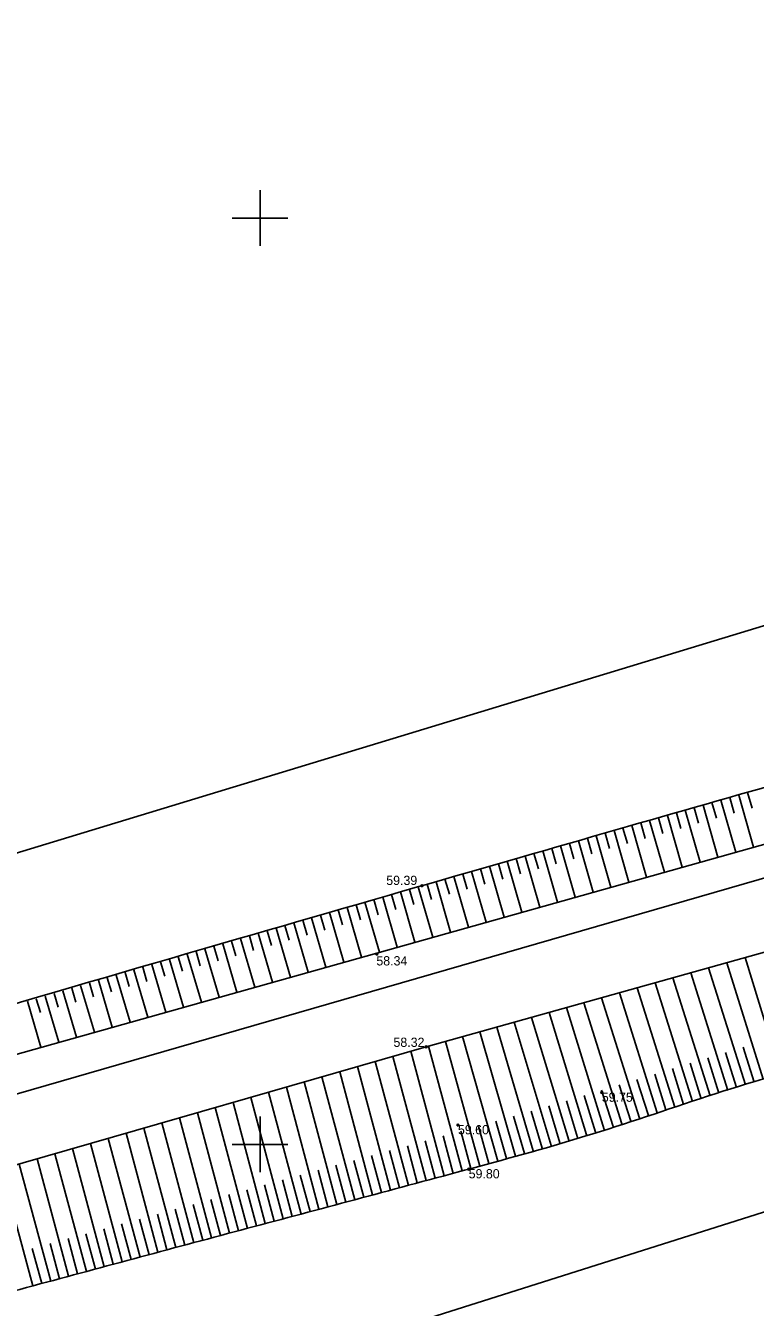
# Model space of a CAD drawing. Extents: x 616607 to 617499, y 408385 to 409695.
# Drawn here: x 616837.3 to 616876.8, y 408541.2 to 408610.4 of the extents above; entities that cross this region are included whole.
import ezdxf

# ---------------------------------------------------------------- set-up
doc = ezdxf.new("R2010")
doc.units = 0
for name, color, linetype in [('GEOD_ELEM_####_####_#', 7, 'Continuous'), ('HIDG_GRAV_####_####_#', 7, 'Continuous'), ('RAMI_UZMR_####_####_#', 7, 'Continuous'), ('RELJ_AATZ_####_TKST_#', 7, 'Continuous'), ('RELJ_ELEM_####_####_#', 7, 'Continuous'), ('RELJ_NOGA_####_####_#', 7, 'Continuous'), ('ROBZ_IERR_####_####_#', 7, 'Continuous'), ('ROBZ_UZMR_####_####_#', 7, 'Continuous')]:
    doc.layers.add(name, color=color, linetype=linetype)

# ---------------------------------------------------------------- blocks, each defined once
blk = doc.blocks.new('PKT')
at = {"layer": 'RELJ_ELEM_####_####_#'}
blk.add_circle((0, 0), 0.05, dxfattribs=at)
blk = doc.blocks.new('KRUSTS')
at = {"layer": 'GEOD_ELEM_####_####_#'}
for p, q in [((0, 1.5), (0, 0)), ((-1.5, 0), (0, 0)), ((0, 0), (0, -1.5)), ((0, 0), (1.5, 0))]:
    blk.add_line(p, q, dxfattribs=at)

msp = doc.modelspace()

# ---------------------------------------------------------------- linework, layer by layer
at = {"layer": 'HIDG_GRAV_####_####_#'}
for points in [[(616726.56, 408522.413), (616768.796, 408535.775), (616917.84, 408577.602)], [(616935.727, 408576.737), (616858.974, 408555.268), (616829.937, 408546.914), (616828.609, 408549.04), (616825.59, 408548.927), (616826.098, 408546.263), (616824.758, 408545.383), (616765.45, 408526.57), (616717.618, 408497.675)]]:
    msp.add_lwpolyline(points, dxfattribs=at)
at = {"layer": 'RAMI_UZMR_####_####_#'}
for points in [[(617191.828, 409115.62), (617145.545, 408952.8), (617072.809, 408766.141), (616965.332, 408652.076), (616939.432, 408594.661), (616924.839, 408592.467), (616706.433, 408526.081), (616666.426, 408467.691)], [(616666.426, 408467.691), (616675.529, 408457.882), (616687.228, 408463.356), (616723.888, 408465.775), (616753.554, 408507.232), (616948.282, 408568.831), (616981.528, 408608.531), (617014.563, 408672.892), (617101.571, 408748.246), (617213.472, 409074.039)]]:
    msp.add_lwpolyline(points, dxfattribs=at)
at = {"layer": 'RELJ_NOGA_####_####_#'}
for p, q in [((616876.333, 408568.996), (616876.573, 408568.151)), ((616876.333, 408568.996), (616876.333, 408568.996)), ((616873.928, 408568.311), (616874.729, 408565.504)), ((616873.928, 408568.311), (616873.928, 408568.31)), ((616874.409, 408568.448), (616874.649, 408567.605)), ((616874.409, 408568.448), (616874.409, 408568.448)), ((616874.89, 408568.585), (616875.691, 408565.773)), ((616874.89, 408568.585), (616874.89, 408568.584)), ((616875.371, 408568.722), (616875.611, 408567.878)), ((616875.371, 408568.722), (616875.371, 408568.722)), ((616875.852, 408568.859), (616876.653, 408566.044)), ((616875.852, 408568.859), (616875.852, 408568.858)), ((616871.524, 408567.626), (616871.763, 408566.786)), ((616871.524, 408567.626), (616871.524, 408567.625)), ((616872.005, 408567.763), (616872.803, 408564.963)), ((616872.005, 408567.763), (616872.005, 408567.762)), ((616872.486, 408567.9), (616872.725, 408567.059)), ((616872.486, 408567.9), (616872.486, 408567.9)), ((616872.967, 408568.037), (616873.766, 408565.233)), ((616872.967, 408568.037), (616872.967, 408568.036)), ((616873.447, 408568.174), (616873.687, 408567.332)), ((616873.447, 408568.174), (616873.447, 408568.174)), ((616869.12, 408566.939), (616869.916, 408564.153)), ((616869.12, 408566.939), (616869.12, 408566.938)), ((616869.601, 408567.076), (616869.84, 408566.24)), ((616869.601, 408567.076), (616869.601, 408567.076)), ((616870.082, 408567.214), (616870.879, 408564.423)), ((616870.082, 408567.214), (616870.082, 408567.213)), ((616870.562, 408567.351), (616870.802, 408566.513)), ((616870.562, 408567.351), (616870.563, 408567.351)), ((616871.043, 408567.488), (616871.842, 408564.693)), ((616871.043, 408567.488), (616871.044, 408567.487)), ((616866.717, 408566.252), (616866.955, 408565.42)), ((616866.717, 408566.252), (616866.717, 408566.251)), ((616867.197, 408566.389), (616867.991, 408563.613)), ((616867.197, 408566.389), (616867.197, 408566.388)), ((616867.678, 408566.527), (616867.916, 408565.693)), ((616867.678, 408566.527), (616867.678, 408566.527)), ((616868.159, 408566.664), (616868.954, 408563.883)), ((616868.159, 408566.664), (616868.159, 408566.663)), ((616868.639, 408566.802), (616868.878, 408565.967)), ((616868.639, 408566.802), (616868.639, 408566.802)), ((616864.313, 408565.563), (616865.104, 408562.803)), ((616864.313, 408565.563), (616864.313, 408565.562)), ((616864.794, 408565.701), (616865.031, 408564.872)), ((616864.794, 408565.701), (616864.794, 408565.701)), ((616865.274, 408565.839), (616866.067, 408563.073)), ((616865.274, 408565.839), (616865.275, 408565.838)), ((616865.755, 408565.976), (616865.993, 408565.146)), ((616865.755, 408565.976), (616865.755, 408565.976)), ((616866.236, 408566.114), (616867.029, 408563.343)), ((616866.236, 408566.114), (616866.236, 408566.113)), ((616861.91, 408564.874), (616862.147, 408564.05)), ((616861.91, 408564.874), (616861.91, 408564.873)), ((616862.391, 408565.012), (616863.18, 408562.262)), ((616862.391, 408565.012), (616862.391, 408565.011)), ((616862.871, 408565.15), (616863.108, 408564.324)), ((616862.871, 408565.15), (616862.871, 408565.149)), ((616863.352, 408565.287), (616864.143, 408562.533)), ((616863.352, 408565.287), (616863.352, 408565.287)), ((616863.833, 408565.425), (616864.07, 408564.598)), ((616863.833, 408565.425), (616863.833, 408565.425)), ((616859.508, 408564.183), (616860.293, 408561.452)), ((616859.508, 408564.183), (616859.508, 408564.182)), ((616859.988, 408564.321), (616860.224, 408563.501)), ((616859.988, 408564.321), (616859.988, 408564.321)), ((616860.469, 408564.459), (616861.256, 408561.723)), ((616860.469, 408564.459), (616860.469, 408564.458)), ((616860.949, 408564.597), (616861.185, 408563.775)), ((616860.949, 408564.597), (616860.949, 408564.597)), ((616861.43, 408564.736), (616862.218, 408561.993)), ((616861.43, 408564.736), (616861.43, 408564.735)), ((616857.105, 408563.49), (616857.341, 408562.677)), ((616857.105, 408563.49), (616857.105, 408563.49)), ((616857.586, 408563.629), (616858.369, 408560.912)), ((616857.586, 408563.629), (616857.586, 408563.628)), ((616858.066, 408563.768), (616858.301, 408562.952)), ((616858.066, 408563.768), (616858.066, 408563.767)), ((616858.547, 408563.906), (616859.332, 408561.183)), ((616858.547, 408563.906), (616858.547, 408563.905)), ((616859.027, 408564.045), (616859.262, 408563.226)), ((616859.027, 408564.045), (616859.027, 408564.044)), ((616854.704, 408562.795), (616855.484, 408560.103)), ((616854.704, 408562.795), (616854.704, 408562.794)), ((616855.184, 408562.934), (616855.419, 408562.126)), ((616855.184, 408562.934), (616855.184, 408562.934)), ((616855.664, 408563.074), (616856.446, 408560.373)), ((616855.664, 408563.074), (616855.665, 408563.073)), ((616856.145, 408563.213), (616856.379, 408562.401)), ((616856.145, 408563.213), (616856.145, 408563.212)), ((616856.625, 408563.351), (616857.408, 408560.643)), ((616856.625, 408563.351), (616856.625, 408563.351)), ((616852.303, 408562.097), (616852.536, 408561.297)), ((616852.303, 408562.097), (616852.303, 408562.097)), ((616852.783, 408562.237), (616853.562, 408559.563)), ((616852.783, 408562.237), (616852.784, 408562.236)), ((616853.263, 408562.377), (616853.497, 408561.573)), ((616853.263, 408562.377), (616853.264, 408562.377)), ((616853.744, 408562.516), (616854.523, 408559.833)), ((616853.744, 408562.516), (616853.744, 408562.515)), ((616854.224, 408562.656), (616854.458, 408561.85)), ((616854.224, 408562.656), (616854.224, 408562.656)), ((616849.903, 408561.397), (616850.676, 408558.754)), ((616849.903, 408561.397), (616849.904, 408561.396)), ((616850.383, 408561.538), (616850.615, 408560.743)), ((616850.383, 408561.538), (616850.383, 408561.537)), ((616850.863, 408561.678), (616851.638, 408559.023)), ((616850.863, 408561.678), (616850.864, 408561.677)), ((616851.343, 408561.818), (616851.576, 408561.02)), ((616851.343, 408561.818), (616851.343, 408561.817)), ((616851.823, 408561.958), (616852.599, 408559.293)), ((616851.823, 408561.958), (616851.824, 408561.957)), ((616847.504, 408560.695), (616847.734, 408559.91)), ((616847.504, 408560.695), (616847.504, 408560.695)), ((616847.984, 408560.836), (616848.752, 408558.213)), ((616847.984, 408560.836), (616847.984, 408560.835)), ((616848.464, 408560.976), (616848.694, 408560.188)), ((616848.464, 408560.976), (616848.464, 408560.976)), ((616848.944, 408561.117), (616849.714, 408558.484)), ((616848.944, 408561.117), (616848.944, 408561.116)), ((616849.423, 408561.257), (616849.655, 408560.465)), ((616849.423, 408561.257), (616849.423, 408561.257)), ((616845.105, 408559.991), (616845.866, 408557.404)), ((616845.105, 408559.991), (616845.106, 408559.99)), ((616845.585, 408560.132), (616845.814, 408559.354)), ((616845.585, 408560.132), (616845.585, 408560.131)), ((616846.065, 408560.273), (616846.829, 408557.674)), ((616846.065, 408560.273), (616846.065, 408560.272)), ((616846.544, 408560.413), (616846.774, 408559.632)), ((616846.544, 408560.413), (616846.545, 408560.413)), ((616847.024, 408560.554), (616847.79, 408557.944)), ((616847.024, 408560.554), (616847.025, 408560.553)), ((616878.128, 408553.811), (616876.199, 408560.086)), ((616842.707, 408559.285), (616842.933, 408558.518)), ((616842.707, 408559.285), (616842.707, 408559.284)), ((616843.187, 408559.426), (616843.941, 408556.864)), ((616843.187, 408559.426), (616843.187, 408559.425)), ((616843.666, 408559.567), (616843.893, 408558.797)), ((616843.666, 408559.567), (616843.666, 408559.567)), ((616844.146, 408559.708), (616844.904, 408557.134)), ((616844.146, 408559.708), (616844.146, 408559.707)), ((616844.626, 408559.85), (616844.853, 408559.075)), ((616844.626, 408559.85), (616844.626, 408559.849)), ((616875.265, 408552.917), (616873.264, 408559.265)), ((616876.218, 408553.217), (616874.228, 408559.535)), ((616877.173, 408553.516), (616875.216, 408559.811)), ((616840.309, 408558.577), (616841.054, 408556.053)), ((616840.309, 408558.577), (616840.31, 408558.576)), ((616840.789, 408558.719), (616841.013, 408557.96)), ((616840.789, 408558.719), (616840.789, 408558.718)), ((616841.268, 408558.86), (616842.017, 408556.324)), ((616841.268, 408558.86), (616841.269, 408558.859)), ((616841.748, 408559.002), (616841.973, 408558.239)), ((616841.748, 408559.002), (616841.748, 408559.001)), ((616842.227, 408559.143), (616842.98, 408556.594)), ((616842.227, 408559.143), (616842.228, 408559.142)), ((616873.357, 408552.316), (616871.337, 408558.726)), ((616874.311, 408552.616), (616872.3, 408558.996)), ((616837.912, 408557.868), (616838.133, 408557.121)), ((616837.912, 408557.868), (616837.912, 408557.868)), ((616838.391, 408558.01), (616839.13, 408555.513)), ((616838.391, 408558.01), (616838.392, 408558.009)), ((616838.871, 408558.152), (616839.093, 408557.401)), ((616838.871, 408558.152), (616838.871, 408558.151)), ((616839.35, 408558.294), (616840.093, 408555.783)), ((616839.35, 408558.294), (616839.351, 408558.293)), ((616839.83, 408558.435), (616840.053, 408557.68)), ((616839.83, 408558.435), (616839.83, 408558.435)), ((616870.496, 408551.414), (616868.446, 408557.918)), ((616871.45, 408551.715), (616869.41, 408558.187)), ((616872.403, 408552.015), (616870.373, 408558.457)), ((616837.432, 408557.726), (616838.167, 408555.243)), ((616837.432, 408557.726), (616837.433, 408557.725)), ((616868.588, 408550.815), (616866.544, 408557.386)), ((616869.542, 408551.113), (616867.483, 408557.648)), ((616865.718, 408549.939), (616863.727, 408556.598)), ((616866.676, 408550.228), (616864.663, 408556.86)), ((616867.632, 408550.52), (616865.608, 408557.124)), ((616862.838, 408549.102), (616860.939, 408555.818)), ((616863.799, 408549.376), (616861.874, 408556.08)), ((616864.76, 408549.655), (616862.794, 408556.337)), ((616860.909, 408548.572), (616859.094, 408555.302)), ((616861.874, 408548.834), (616860.025, 408555.562)), ((616876.695, 408553.368), (616876.1, 408555.258)), ((616858.012, 408547.793), (616856.222, 408554.477)), ((616858.978, 408548.052), (616857.179, 408554.752)), ((616859.944, 408548.311), (616858.137, 408555.028)), ((616874.788, 408552.766), (616874.186, 408554.676)), ((616875.742, 408553.067), (616875.143, 408554.967)), ((616856.08, 408547.275), (616854.304, 408553.925)), ((616857.046, 408547.534), (616855.261, 408554.2)), ((616871.926, 408551.865), (616871.316, 408553.802)), ((616872.88, 408552.165), (616872.273, 408554.093)), ((616873.834, 408552.466), (616873.229, 408554.384)), ((616853.182, 408546.502), (616851.424, 408553.096)), ((616854.148, 408546.76), (616852.385, 408553.373)), ((616855.114, 408547.017), (616853.342, 408553.648)), ((616870.019, 408551.264), (616869.403, 408553.22)), ((616870.973, 408551.564), (616870.359, 408553.511)), ((616875.742, 408553.067), (616875.741, 408553.067)), ((616876.218, 408553.217), (616876.218, 408553.218)), ((616876.695, 408553.368), (616876.695, 408553.368)), ((616851.249, 408545.987), (616849.501, 408552.543)), ((616852.215, 408546.244), (616850.462, 408552.819)), ((616867.154, 408550.373), (616866.548, 408552.359)), ((616868.11, 408550.667), (616867.498, 408552.643)), ((616869.065, 408550.963), (616868.446, 408552.928)), ((616873.834, 408552.466), (616873.834, 408552.466)), ((616874.311, 408552.616), (616874.311, 408552.617)), ((616874.788, 408552.766), (616874.788, 408552.767)), ((616875.265, 408552.917), (616875.264, 408552.918)), ((616848.35, 408545.214), (616846.617, 408551.713)), ((616849.317, 408545.471), (616847.578, 408551.99)), ((616850.283, 408545.729), (616848.54, 408552.266)), ((616865.239, 408549.797), (616864.645, 408551.798)), ((616866.197, 408550.083), (616865.598, 408552.077)), ((616871.45, 408551.715), (616871.449, 408551.715)), ((616871.926, 408551.865), (616871.926, 408551.865)), ((616872.403, 408552.015), (616872.403, 408552.016)), ((616872.88, 408552.165), (616872.88, 408552.166)), ((616873.357, 408552.316), (616873.357, 408552.317)), ((616846.418, 408544.698), (616844.691, 408551.159)), ((616847.384, 408544.956), (616845.653, 408551.436)), ((616862.356, 408548.967), (616861.796, 408550.985)), ((616863.319, 408549.238), (616862.744, 408551.251)), ((616864.28, 408549.515), (616863.694, 408551.522)), ((616869.065, 408550.963), (616869.065, 408550.963)), ((616869.542, 408551.113), (616869.542, 408551.114)), ((616870.019, 408551.264), (616870.019, 408551.264)), ((616870.496, 408551.414), (616870.496, 408551.415)), ((616870.973, 408551.564), (616870.973, 408551.565)), ((616843.52, 408543.921), (616841.8, 408550.327)), ((616844.486, 408544.18), (616842.763, 408550.604)), ((616845.452, 408544.439), (616843.727, 408550.882)), ((616860.426, 408548.441), (616859.882, 408550.458)), ((616861.392, 408548.702), (616860.843, 408550.721)), ((616867.154, 408550.373), (616867.154, 408550.373)), ((616867.632, 408550.52), (616867.632, 408550.52)), ((616868.11, 408550.667), (616868.11, 408550.667)), ((616868.588, 408550.815), (616868.587, 408550.816)), ((616841.589, 408543.402), (616839.878, 408549.774)), ((616842.555, 408543.662), (616840.839, 408550.051)), ((616857.529, 408547.663), (616856.993, 408549.666)), ((616858.495, 408547.922), (616857.956, 408549.93)), ((616859.461, 408548.182), (616858.919, 408550.194)), ((616864.76, 408549.655), (616864.759, 408549.656)), ((616865.239, 408549.797), (616865.239, 408549.797)), ((616865.718, 408549.939), (616865.718, 408549.94)), ((616866.197, 408550.083), (616866.197, 408550.083)), ((616866.676, 408550.228), (616866.676, 408550.229)), ((616838.691, 408542.624), (616836.994, 408548.944)), ((616839.657, 408542.884), (616837.956, 408549.221)), ((616840.623, 408543.143), (616838.917, 408549.498)), ((616854.631, 408546.888), (616854.101, 408548.875)), ((616855.597, 408547.146), (616855.065, 408549.138)), ((616856.563, 408547.405), (616856.028, 408549.402)), ((616862.356, 408548.967), (616862.356, 408548.967)), ((616862.838, 408549.102), (616862.837, 408549.103)), ((616863.319, 408549.238), (616863.319, 408549.238)), ((616863.799, 408549.376), (616863.799, 408549.377)), ((616864.28, 408549.515), (616864.28, 408549.515)), ((616837.726, 408542.365), (616836.033, 408548.668)), ((616852.698, 408546.373), (616852.172, 408548.349)), ((616853.665, 408546.631), (616853.137, 408548.612)), ((616859.461, 408548.182), (616859.461, 408548.182)), ((616859.944, 408548.311), (616859.943, 408548.312)), ((616860.426, 408548.441), (616860.426, 408548.442)), ((616860.909, 408548.572), (616860.909, 408548.573)), ((616861.392, 408548.702), (616861.392, 408548.702)), ((616861.874, 408548.834), (616861.874, 408548.835)), ((616849.8, 408545.6), (616849.278, 408547.559)), ((616850.766, 408545.858), (616850.242, 408547.822)), ((616851.732, 408546.116), (616851.207, 408548.085)), ((616857.046, 408547.534), (616857.046, 408547.535)), ((616857.529, 408547.663), (616857.529, 408547.664)), ((616858.012, 408547.793), (616858.012, 408547.794)), ((616858.495, 408547.922), (616858.495, 408547.922)), ((616858.978, 408548.052), (616858.978, 408548.053)), ((616847.867, 408545.085), (616847.347, 408547.032)), ((616848.833, 408545.343), (616848.313, 408547.295)), ((616854.631, 408546.888), (616854.631, 408546.889)), ((616855.114, 408547.017), (616855.114, 408547.018)), ((616855.597, 408547.146), (616855.597, 408547.147)), ((616856.08, 408547.275), (616856.08, 408547.276)), ((616856.563, 408547.405), (616856.563, 408547.405)), ((616844.969, 408544.31), (616844.452, 408546.24)), ((616845.935, 408544.568), (616845.417, 408546.504)), ((616846.901, 408544.827), (616846.382, 408546.768)), ((616851.732, 408546.116), (616851.732, 408546.116)), ((616852.215, 408546.244), (616852.215, 408546.245)), ((616852.698, 408546.373), (616852.698, 408546.373)), ((616853.182, 408546.502), (616853.181, 408546.503)), ((616853.665, 408546.631), (616853.665, 408546.631)), ((616854.148, 408546.76), (616854.148, 408546.761)), ((616842.072, 408543.532), (616841.558, 408545.446)), ((616843.037, 408543.791), (616842.522, 408545.711)), ((616844.003, 408544.051), (616843.487, 408545.975)), ((616849.317, 408545.471), (616849.316, 408545.472)), ((616849.8, 408545.6), (616849.8, 408545.601)), ((616850.283, 408545.729), (616850.283, 408545.73)), ((616850.766, 408545.858), (616850.766, 408545.858)), ((616851.249, 408545.987), (616851.249, 408545.988)), ((616840.14, 408543.013), (616839.629, 408544.917)), ((616841.106, 408543.273), (616840.593, 408545.182)), ((616846.901, 408544.827), (616846.901, 408544.827)), ((616847.384, 408544.956), (616847.384, 408544.957)), ((616847.867, 408545.085), (616847.867, 408545.085)), ((616848.35, 408545.214), (616848.35, 408545.215)), ((616848.833, 408545.343), (616848.833, 408545.343)), ((616838.209, 408542.495), (616837.7, 408544.388)), ((616839.174, 408542.754), (616838.664, 408544.653)), ((616844.003, 408544.051), (616844.003, 408544.051)), ((616844.486, 408544.18), (616844.486, 408544.181)), ((616844.969, 408544.31), (616844.969, 408544.31)), ((616845.452, 408544.439), (616845.452, 408544.44)), ((616845.935, 408544.568), (616845.935, 408544.569)), ((616846.418, 408544.698), (616846.418, 408544.699)), ((616841.589, 408543.402), (616841.588, 408543.403)), ((616842.072, 408543.532), (616842.072, 408543.532)), ((616842.555, 408543.662), (616842.554, 408543.663)), ((616843.037, 408543.791), (616843.037, 408543.792)), ((616843.52, 408543.921), (616843.52, 408543.922)), ((616839.174, 408542.754), (616839.174, 408542.754)), ((616839.657, 408542.884), (616839.657, 408542.885)), ((616840.14, 408543.013), (616840.14, 408543.014)), ((616840.623, 408543.143), (616840.623, 408543.144)), ((616841.106, 408543.273), (616841.106, 408543.273)), ((616837.726, 408542.365), (616837.725, 408542.366)), ((616838.209, 408542.495), (616838.208, 408542.495)), ((616838.691, 408542.624), (616838.691, 408542.625))]:
    msp.add_line(p, q, dxfattribs=at)
msp.add_open_spline([(616975.731, 408606.41), (616971.71, 408604.144), (616967.689, 408601.878), (616963.668, 408599.612), (616962.341, 408598.864), (616961.192, 408597.791), (616960.311, 408596.511), (616959.39, 408595.173), (616958.675, 408593.776), (616958.002, 408592.329), (616957.302, 408590.825), (616956.736, 408589.272), (616956.015, 408587.778), (616955.313, 408586.324), (616954.582, 408584.882), (616953.626, 408583.572), (616952.496, 408582.025), (616951.261, 408580.593), (616950.022, 408579.143), (616948.785, 408577.695), (616947.537, 408576.278), (616946.22, 408574.895), (616945.626, 408574.271), (616944.957, 408573.742), (616944.225, 408573.278), (616943.451, 408572.788), (616942.648, 408572.387), (616941.804, 408572.051), (616941, 408571.73), (616940.2, 408571.414), (616939.368, 408571.187), (616938.69, 408571.002), (616938.005, 408570.852), (616937.329, 408570.663), (616918.615, 408565.441), (616899.903, 408560.204), (616881.253, 408554.75), (616874.57, 408552.796), (616867.991, 408550.484), (616861.269, 408548.669), (616855.483, 408547.106), (616849.688, 408545.577), (616843.9, 408544.023), (616838.111, 408542.469), (616832.323, 408540.916), (616826.537, 408539.352), (616816.497, 408536.637), (616806.51, 408533.737), (616796.541, 408530.774), (616791.553, 408529.292), (616786.584, 408527.751), (616781.609, 408526.226), (616776.622, 408524.697), (616771.656, 408523.11), (616766.688, 408521.515), (616762.607, 408520.204), (616758.677, 408518.521), (616754.775, 408516.687), (616750.921, 408514.875), (616747.341, 408512.653), (616743.915, 408510.109), (616740.341, 408507.454), (616736.942, 408504.677), (616733.801, 408501.555), (616732.131, 408499.895), (616730.49, 408498.223), (616728.926, 408496.468), (616728.114, 408495.556), (616727.318, 408494.632), (616726.518, 408493.709), (616725.695, 408492.76), (616724.91, 408491.864), (616724.122, 408490.803), (616723.665, 408490.187), (616723.18, 408489.459), (616723.332, 408488.764), (616723.537, 408487.829), (616723.949, 408486.896), (616724.213, 408485.954), (616724.975, 408483.236), (616725.742, 408480.486), (616726.381, 408477.738), (616726.631, 408476.667), (616726.554, 408475.507), (616726.221, 408474.429), (616726.043, 408473.855), (616725.77, 408473.346), (616725.415, 408472.86), (616725.226, 408472.602), (616725.032, 408472.37), (616724.813, 408472.14), (616724.582, 408471.898), (616724.347, 408471.683), (616724.071, 408471.48), (616723.783, 408471.268), (616723.475, 408471.091), (616723.13, 408471.039), (616722.812, 408470.991), (616722.494, 408470.986), (616722.176, 408470.982), (616721.543, 408470.975), (616720.901, 408471.154), (616720.278, 408471.02), (616716.569, 408470.219), (616712.93, 408469.339), (616709.261, 408468.478), (616707.424, 408468.047), (616705.589, 408467.613), (616703.751, 408467.182), (616701.927, 408466.754), (616700.076, 408466.424), (616698.236, 408466.115), (616695.42, 408465.64), (616692.315, 408465.565), (616689.691, 408467.073), (616684.319, 408470.158), (616679.892, 408473.486), (616675.008, 408476.777), (616674.831, 408476.896), (616674.652, 408477.012), (616674.483, 408477.14), (616674.175, 408477.376), (616674.46, 408477.978), (616674.696, 408478.288), (616675.427, 408479.251), (616676.165, 408480.2), (616676.939, 408481.135), (616677.893, 408482.289), (616678.812, 408483.429), (616679.848, 408484.532), (616681.078, 408485.839), (616682.698, 408486.726), (616684.412, 408487.237), (616686.183, 408487.764), (616687.958, 408488.143), (616689.768, 408488.401), (616691.642, 408488.668), (616693.528, 408488.826), (616695.398, 408489.116), (616696.323, 408489.26), (616697.239, 408489.444), (616698.155, 408489.647), (616699.054, 408489.848), (616699.912, 408490.166), (616700.785, 408490.476), (616703.122, 408491.305), (616705.613, 408491.942), (616707.248, 408494.043), (616707.429, 408494.275), (616707.474, 408494.537), (616707.552, 408494.798), (616707.628, 408495.051), (616707.711, 408495.3), (616707.761, 408495.559), (616707.86, 408496.068), (616707.943, 408496.577), (616707.977, 408497.092), (616708.044, 408498.12), (616708.108, 408499.147), (616708.168, 408500.175), (616708.254, 408501.63), (616708.34, 408503.085), (616708.414, 408504.54), (616708.488, 408505.998), (616708.403, 408507.461), (616708.436, 408508.92), (616708.468, 408510.38), (616708.539, 408511.837), (616708.686, 408513.293), (616708.76, 408514.026), (616708.887, 408514.749), (616709.039, 408515.47), (616709.116, 408515.834), (616709.208, 408516.193), (616709.297, 408516.554), (616709.387, 408516.92), (616709.487, 408517.278), (616709.619, 408517.635), (616710.681, 408520.51), (616712.959, 408522.898), (616715.736, 408524.335), (616718.688, 408525.863), (616721.668, 408526.887), (616724.792, 408527.643), (616730.078, 408528.922), (616735.359, 408530.207), (616740.655, 408531.436), (616749.901, 408533.581), (616759.244, 408535.317), (616768.413, 408537.779), (616798.7, 408545.91), (616828.618, 408555.288), (616858.746, 408563.964), (616877.646, 408569.406), (616896.581, 408574.731), (616915.501, 408580.089), (616916.131, 408580.267), (616916.803, 408580.127), (616917.44, 408580.402), (616917.832, 408580.571), (616918.181, 408580.992), (616918.136, 408581.394), (616918.071, 408581.969), (616918.005, 408582.544), (616917.94, 408583.119), (616917.87, 408583.733), (616917.799, 408584.347), (616917.73, 408584.96), (616917.674, 408585.454), (616917.97, 408585.948), (616918.384, 408586.3), (616918.906, 408586.742), (616919.445, 408586.959), (616920.02, 408587.218), (616920.568, 408587.465), (616921.093, 408587.698), (616921.676, 408587.899), (616922.792, 408588.284), (616923.918, 408588.529), (616925.044, 408588.565), (616925.938, 408588.594), (616926.854, 408588.454), (616927.734, 408588.123), (616928.677, 408587.768), (616929.526, 408587.359), (616930.432, 408586.999), (616931.324, 408586.645), (616932.223, 408586.313), (616933.127, 408585.998), (616933.97, 408585.704), (616934.935, 408585.706), (616935.807, 408585.922), (616937.564, 408586.355), (616939.443, 408587.201), (616940.422, 408588.724), (616944.438, 408594.972), (616948.27, 408601.228), (616952.11, 408607.531)], degree=3, dxfattribs=at)
at = {"layer": 'ROBZ_IERR_####_####_#'}
msp.add_lwpolyline([(617055.284, 408797.783), (617087.528, 408757.04), (616999.181, 408676.019), (616968.565, 408608.405), (616958.517, 408604.593), (616940.576, 408582.801), (616889.795, 408568.012), (616805.459, 408543.657), (616730.494, 408522.344), (616717.135, 408556.579)], dxfattribs=at)
at = {"layer": 'ROBZ_UZMR_####_####_#'}
msp.add_lwpolyline([(616704.998, 408460.626), (616695.309, 408466.84), (616688.046, 408471.498), (616708.653, 408488.203), (616730.494, 408522.344), (616805.459, 408543.657), (616889.795, 408568.012), (616940.576, 408582.801), (616958.517, 408604.593), (616968.565, 408608.405), (616974.837, 408605.827), (616993.227, 408598.268)], dxfattribs=at)

# ---------------------------------------------------------------- block references
at = {"layer": 'GEOD_ELEM_####_####_#'}
for p in [(616850, 408600), (616850, 408550)]:
    msp.add_blockref('KRUSTS', p, dxfattribs=at)
at = {"layer": 'RELJ_ELEM_####_####_#'}
for p in [(616858.746, 408563.964), (616856.309, 408560.278), (616858.974, 408555.268), (616868.46, 408552.803), (616860.689, 408551.047), (616861.269, 408548.669)]:
    msp.add_blockref('PKT', p, dxfattribs=at)

# ---------------------------------------------------------------- texts
at = {"layer": 'RELJ_AATZ_####_TKST_#'}
for s, p in [('59.39', (616856.817, 408564.003)), ('58.34', (616856.282, 408559.662)), ('58.32', (616857.207, 408555.265)), ('59.75', (616868.46, 408552.303)), ('59.60', (616860.689, 408550.547)), ('59.80', (616861.269, 408548.169))]:
    msp.add_text(s, height=0.5, dxfattribs=at).set_placement(p)

doc.saveas('drawing.dxf')
